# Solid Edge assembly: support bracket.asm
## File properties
Author: vicky raina
Template: normal.asm
Last saved by: Robert a Rhodes jr
Revision: 2
Application: Solid Edge
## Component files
adjusting_nut_handle.par
adjusting_screw_guide.par
Stock_support_base.par
thrust_bearing.par
adjusting_screw_nut.par
support_adjusting_screw.par
support_roller_bracket.par
stock_support_roller.par
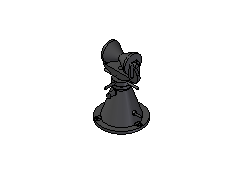
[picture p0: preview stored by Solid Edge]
